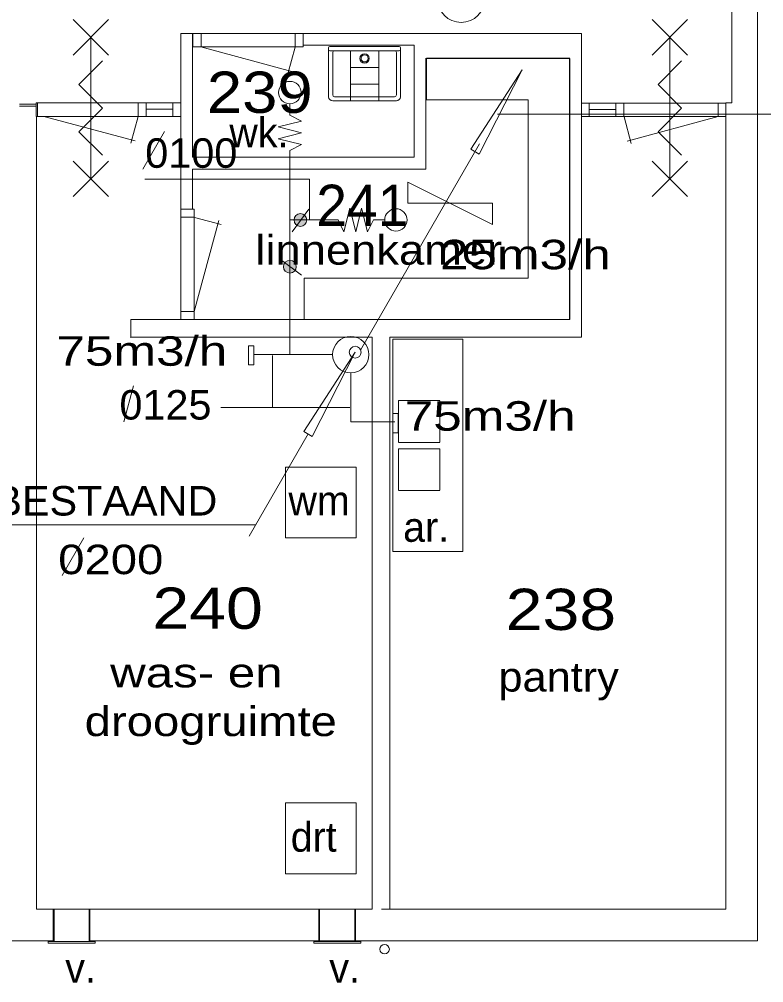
# Model space of a CAD drawing. Extents: x 295824 to 414724, y 24924 to 109024.
# Drawn here: x 325944 to 332262, y 87199 to 95369 of the extents above; entities that cross this region are included whole.
import ezdxf

# ---------------------------------------------------------------- set-up
doc = ezdxf.new("R2010")
doc.units = 0
doc.header["$LTSCALE"] = 100
doc.linetypes.add('MEDIUM_DASHED', pattern=[4.5, 3, -1.5])
for name, color, linetype, lineweight in [('1', 7, 'Continuous', 13), ('24', 7, 'Continuous', 13), ('61', 7, 'Continuous', 13)]:
    doc.layers.add(name, color=color, linetype=linetype, lineweight=lineweight)

msp = doc.modelspace()

# ---------------------------------------------------------------- hatches: boundary and pattern name
at = {"layer": '24'}
for points in [[(328329.9, 93612.9, 1), (328329.9, 93721.5, 1)], [(328294.6, 93270.4, 1), (328186, 93270.4, 1)]]:
    msp.add_hatch(color=256, dxfattribs=at).paths.add_polyline_path(points)

# ---------------------------------------------------------------- linework, layer by layer
at = {"layer": '1'}
msp.add_line((327895.1, 90987.1), (328395.1, 91853.1), dxfattribs=at)
msp.add_lwpolyline([(328795.1, 92546.1), (328431.1, 91832.1), (328359.1, 91874.1)], close=True, dxfattribs=at)
msp.add_circle((328795.1, 92545.8), 50, dxfattribs=at)
at = {"layer": '24'}
for p, q in [((330003.8, 94565.6), (337978.3, 94565.6)), ((327175.7, 94418.2), (326991.3, 94098.9)), ((328839.4, 92562.5), (329850, 94312.8)), ((328240.3, 94205.8), (328240.3, 92525)), ((328400.7, 93758.8), (328259, 93567.3)), ((328599, 93667.2), (328240.3, 93667.2)), ((328148.7, 93341.2), (328340.2, 93199.6)), ((328603, 92525), (327940.5, 92525)), ((328093.9, 92517.6), (328093.9, 92077.1)), ((326912.8, 92260.5), (326830.7, 91954)), ((328748, 92077.1), (327653.6, 92077.1)), ((325591.5, 91082.6), (327952.3, 91082.6)), ((326491.7, 90972.4), (326307.4, 90653.1))]:
    msp.add_line(p, q, dxfattribs=at)
for points in [[(330211.2, 94939.7), (329847.2, 94225.7), (329775.2, 94267.7)], [(329960.4, 93628.8), (329960.4, 93808.8), (329240.4, 93808.8), (329240.4, 93988.8)], [(327890.5, 92437.6), (327934, 92437.6), (327934, 92599.9), (327890.5, 92599.9)], [(329114.7, 91862.6), (329158.2, 91862.6), (329158.2, 92024.9), (329114.7, 92024.9)]]:
    msp.add_lwpolyline(points, close=True, dxfattribs=at)
for points in [[(328240.3, 94655.8), (328240.3, 94555.8), (328340.3, 94505.8), (328140.3, 94455.8), (328340.3, 94405.8), (328140.3, 94355.8), (328340.3, 94305.8), (328240.3, 94255.8), (328240.3, 94205.8)], [(328408.3, 93666.2), (328408.3, 94012.4), (327008.9, 94012.4)], [(329049, 93667.2), (328949, 93667.2), (328899, 93567.2), (328849, 93767.2), (328799, 93567.2), (328749, 93767.2), (328699, 93567.2), (328649, 93667.2), (328599, 93667.2)], [(328756.6, 92371.5), (328756.6, 91954.2), (329131.4, 91954.2)]]:
    msp.add_lwpolyline(points, dxfattribs=at)
for centre, radius in [((328240.3, 94747.4), 95), ((328329.9, 93667.2), 54.3), ((329140.7, 93667.2), 95), ((328240.3, 93270.4), 54.3), ((328756.6, 92525), 153.6)]:
    msp.add_circle(centre, radius, dxfattribs=at)
at = {"layer": '61'}
for p, q in [((332210.1, 104417.6), (332210.1, 87553.4)), ((331990.1, 99122.6), (331990.1, 94659.1)), ((326700.5, 95365.7), (326400.5, 95065.7)), ((326400.5, 95365.7), (326700.5, 95065.7)), ((331615.3, 95365.7), (331315.3, 95065.7)), ((331315.3, 95365.7), (331615.3, 95065.7)), ((326550.5, 94015.7), (326550.5, 95215.7)), ((327315.1, 95248.4), (327315.1, 94648.4)), ((327415.1, 95248.4), (327315.1, 95248.4)), ((328353.5, 95248.6), (327418.2, 95248.6)), ((327486.5, 95248.6), (327486.5, 95134.6)), ((328286.5, 95248.6), (328286.5, 95134.6)), ((328353.5, 95248.6), (328353.5, 95134.6)), ((330715.1, 95248.4), (328354.5, 95248.4)), ((328354.5, 95148.4), (328354.5, 95248.4)), ((330715.1, 94648.4), (330715.1, 95248.4)), ((331465.3, 94015.7), (331465.3, 95215.7)), ((327485.7, 95134), (328258.5, 94926.9)), ((328284.1, 95133.4), (328223.4, 94906.5)), ((328354.5, 95148.4), (329295.1, 95148.4)), ((328569.4, 95127.1), (328569.4, 94712.1)), ((329169.4, 95137.1), (328579.4, 95137.1)), ((328579.4, 95102.1), (329169.4, 95102.1)), ((328754.4, 95102.1), (328754.4, 94677.1)), ((328994.4, 95102.1), (328994.4, 94677.1)), ((329179.4, 94712.1), (329179.4, 95127.1)), ((329295.1, 95148.4), (329295.1, 94198.4)), ((328604.4, 94727.1), (328604.4, 95087.1)), ((329144.4, 95087.1), (329144.4, 94727.1)), ((329401.2, 95038.4), (330615.1, 95038.4)), ((329401.2, 95037.2), (330613.7, 95037.2)), ((329401.2, 94687.2), (329401.2, 95037.2)), ((330615.1, 95037.2), (330615.1, 92823.4)), ((328754.4, 94960.4), (328994.4, 94960.4)), ((328754.4, 94818.8), (328994.4, 94818.8)), ((329129.4, 94712.1), (328619.4, 94712.1)), ((325944.5, 94633.3), (326085.7, 94633.3)), ((325945.2, 94648.3), (326086.3, 94648.3)), ((326097.9, 94659.6), (326097.9, 94545.6)), ((326954.4, 94659.6), (326954.4, 94545.6)), ((327021.4, 94659.6), (327021.4, 94545.6)), ((327247.4, 94659.6), (327247.4, 94545.6)), ((328604.4, 94677.1), (329144.4, 94677.1)), ((330781, 94658.1), (330781, 94544.1)), ((331007, 94658.1), (331007, 94544.1)), ((331074, 94658.1), (331074, 94544.1)), ((331874, 94658.1), (331874, 94544.1)), ((331940.1, 94659.1), (331940.1, 87823.4)), ((331990.1, 94659.1), (331940.1, 94659.1)), ((326090.1, 94548.4), (326090.1, 87823.4)), ((326153.6, 94545), (326926.4, 94337.9)), ((326952.1, 94544.3), (326891.3, 94317.5)), ((327247.4, 94605.5), (327021.4, 94605.5)), ((327315.1, 93758.6), (327315.1, 94548.4)), ((330781, 94604), (331007, 94604)), ((331076.3, 94542.9), (331137.1, 94316)), ((331874.7, 94543.5), (331102, 94336.4)), ((326700.5, 94165.7), (326400.5, 93865.7)), ((326400.5, 94165.7), (326700.5, 93865.7)), ((331615.3, 94165.7), (331315.3, 93865.7)), ((331315.3, 94165.7), (331615.3, 93865.7)), ((327314.7, 93758.1), (327428.7, 93758.1)), ((327314.7, 93758.1), (327314.7, 92822.8)), ((327315.1, 93758.6), (327415.1, 93758.6)), ((327314.7, 93691.1), (327428.7, 93691.1)), ((327429.4, 92890.3), (327636.4, 93663.1)), ((327430, 93688.8), (327656.8, 93628)), ((330615.1, 92823.4), (326889.8, 92823.4)), ((326889.8, 92673.4), (326889.8, 92823.4)), ((327314.7, 92891.1), (327428.7, 92891.1)), ((328940.1, 92673.4), (326889.8, 92673.4)), ((329161.9, 92135.7), (329511.9, 92135.7)), ((329512.8, 92134), (329512.8, 91784)), ((329511.9, 91781.5), (329161.9, 91781.5)), ((329161.9, 91727.4), (329511.9, 91727.4)), ((329512.8, 91725.8), (329512.8, 91375.8)), ((329511.9, 91373.3), (329161.9, 91373.3)), ((328940.1, 87823.4), (326090.1, 87823.4)), ((326233, 87553.4), (326233, 87823.4)), ((326239.5, 87548.5), (326239.5, 87822.9)), ((326538.2, 87548.5), (326538.2, 87822.9)), ((326543.7, 87553.4), (326543.7, 87823.4)), ((328486.7, 87553.4), (328486.7, 87823.4)), ((328493.2, 87548.5), (328493.2, 87822.9)), ((328791.9, 87548.5), (328791.9, 87822.9)), ((328797.4, 87553.4), (328797.4, 87823.4)), ((331940.1, 87823.4), (329017.7, 87823.4)), ((326233, 87553.4), (307806, 87553.4)), ((326190.1, 87548.5), (326588.4, 87548.5)), ((326190.1, 87533.4), (326190.1, 87548.5)), ((326190.1, 87533.4), (326588.4, 87533.4)), ((330425.5, 87553.4), (326543.7, 87553.4)), ((326588.4, 87533.4), (326588.4, 87548.5)), ((328443.9, 87548.5), (328842.2, 87548.5)), ((328443.9, 87533.4), (328443.9, 87548.5)), ((328443.9, 87533.4), (328842.2, 87533.4)), ((328842.2, 87533.4), (328842.2, 87548.5)), ((330425.5, 87553.4), (332210.1, 87553.4))]:
    msp.add_line(p, q, dxfattribs=at)
at = {"layer": '61', "linetype": 'MEDIUM_DASHED'}
msp.add_line((326887.5, 92671.8), (326892.1, 92671.8), dxfattribs=at)
at = {"layer": '61'}
for points in [[(329295.1, 94198.4), (327415.1, 94198.4), (327415.1, 95248.4)], [(327418.2, 95248.6), (327418.2, 95134.6), (328353.5, 95134.6)], [(327415.1, 93758.6), (327415.1, 94098.4), (329395.1, 94098.4), (329395.1, 95038.4)], [(330613.7, 95037.2), (330613.7, 92823.5), (328363.1, 92823.5), (328363.1, 93173.5), (330263.7, 93173.5), (330263.7, 94687.2), (329401.2, 94687.2)], [(326650.5, 94215.7), (326450.5, 94415.7), (326650.5, 94615.7), (326450.5, 94815.7), (326650.5, 95015.7)], [(331565.3, 94215.7), (331365.3, 94415.7), (331565.3, 94615.7), (331365.3, 94815.7), (331565.3, 95015.7)], [(329090.1, 87823.4), (329090.1, 92673.4), (330715.1, 92673.4), (330715.1, 94548.4)], [(327314.7, 92822.8), (327428.7, 92822.8), (327428.7, 93758.1)], [(328340.1, 92673.4), (328940.1, 92673.4), (328940.1, 87823.4)], [(329113.6, 90855.7), (329708.3, 90855.7), (329708.3, 92655.7)], [(329113.6, 90855.7), (329113.6, 92655.7), (329708.3, 92655.7)], [(329162.8, 91784), (329162.8, 92134), (329161.9, 92135.7)], [(329162.8, 91375.8), (329162.8, 91725.8), (329161.9, 91727.4)]]:
    msp.add_lwpolyline(points, dxfattribs=at)
for points in [[(326087.4, 94659.6), (326087.4, 94545.6), (327313.8, 94545.6), (327313.8, 94659.6)], [(326087.4, 94659.6), (326087.4, 94545.6), (327313.8, 94545.6), (327313.8, 94659.6)], [(331941, 94658.1), (331941, 94544.1), (330714.6, 94544.1), (330714.6, 94658.1)], [(328203.4, 90970.7), (328203.4, 91570.7), (328803.4, 91570.7), (328803.4, 90970.7)], [(328203.4, 88123.7), (328203.4, 88723.7), (328803.4, 88723.7), (328803.4, 88123.7)]]:
    msp.add_lwpolyline(points, close=True, dxfattribs=at)
for centre, radius in [((329694.2, 95542.7), 200), ((328874.4, 95037.1), 40), ((328874.4, 95037.1), 30), ((329044.8, 87483), 40)]:
    msp.add_circle(centre, radius, dxfattribs=at)
for centre, radius, start, end in [((328579.4, 95127.1), 10, 90, 180), ((328579.4, 95112.1), 10, 180, 270), ((328619.4, 95087.1), 15, 90, 180), ((329129.4, 95087.1), 15, 0, 90), ((329169.4, 95127.1), 10, 0, 90), ((329169.4, 95112.1), 10, 270, 0), ((328604.4, 94712.1), 35, 180, 270), ((328619.4, 94727.1), 15, 180, 270), ((329129.4, 94727.1), 15, 270, 0), ((329144.4, 94712.1), 35, 270, 0)]:
    msp.add_arc(centre, radius, start, end, dxfattribs=at)

# ---------------------------------------------------------------- texts
at = {"layer": '24'}
for s, width, p in [('0100', 1.05, (327013.2, 94109.5)), ('25m3/h', 1.3, (329514.3, 93249.1)), ('75m3/h', 1.3, (326259.5, 92430.9)), ('0125', 1.05, (326794.1, 91974.7)), ('75m3/h', 1.3, (329215.6, 91880.2)), ('BESTAAND', 1.05, (325732.7, 91160.9)), ('0200', 1.2, (326274.2, 90663.6))]:
    msp.add_text(s, height=250, dxfattribs=dict(at, width=width)).set_placement(p)
at = {"layer": '61'}
for s, height, width, p in [('239', 350, 1.15, (327536, 94575.4)), ('linnenkamer', 250, 1.15, (327948.1, 93288)), ('240', 350, 1.2, (327073.9, 90200.2)), ('238', 350, 1.2, (330072.3, 90190.3)), ('was- en ', 250, 1.25, (326715.2, 89703.7)), ('pantry', 250, 1.1, (330010.5, 89668.1)), ('droogruimte', 250, 1.2, (326499, 89290.6))]:
    msp.add_text(s, height=height, dxfattribs=dict(at, width=width)).set_placement(p)
for s, height, p in [('wk.', 250, (327727, 94284.1)), ('241', 350, (328464.9, 93616.2)), ('wm', 250, (328228.4, 91162.5)), ('ar.', 250, (329202.1, 90938.1)), ('drt', 250, (328248, 88310.6)), ('v.', 250, (326334.2, 87199.1)), ('v.', 250, (328575.4, 87199.1))]:
    msp.add_text(s, height=height, dxfattribs=at).set_placement(p)

doc.saveas('drawing.dxf')
